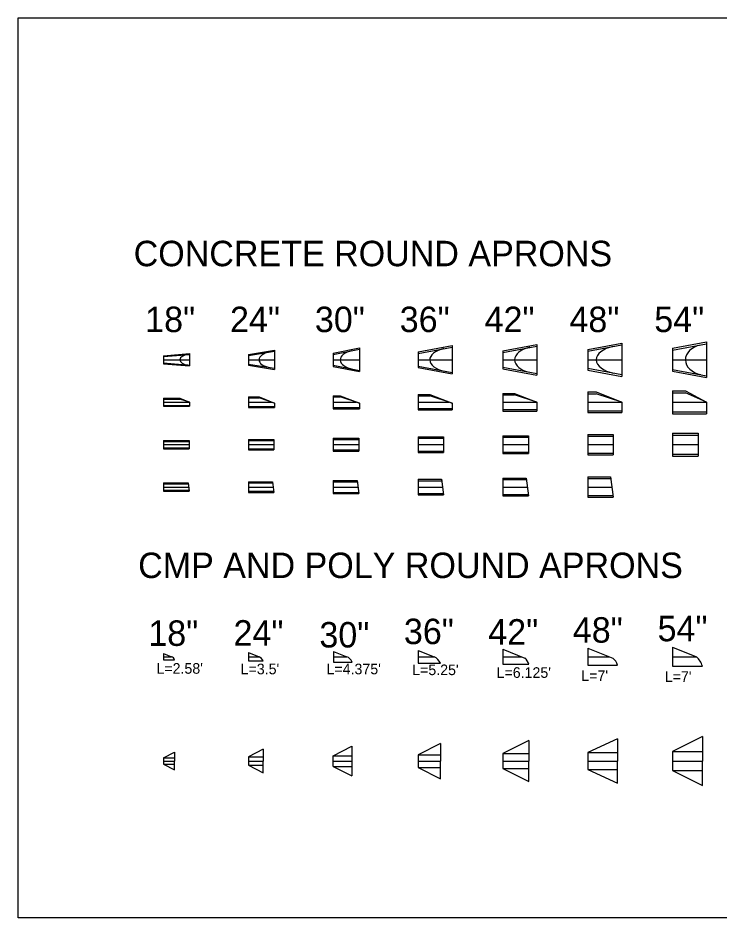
# Model space of a CAD drawing. Extents: x 14089015 to 14094575, y 8545767 to 8546666.
# Drawn here: x 14093936 to 14094101.5, y 8546454.2 to 8546666.4 of the extents above; entities that cross this region are included whole.
import ezdxf

# ---------------------------------------------------------------- set-up
doc = ezdxf.new("R2010")
doc.units = 0
doc.layers.add('CulvertExisting', color=7, linetype='Continuous')

msp = doc.modelspace()

# ---------------------------------------------------------------- linework, layer by layer
at = {"layer": 'CulvertExisting'}
for p, q in [((14094090.34, 8546588.53), (14094098.34, 8546590.03)), ((14094098.34, 8546590.03), (14094098.34, 8546581.6)), ((14093990.34, 8546587.07), (14093996.47, 8546588.07)), ((14093990.34, 8546586.81), (14093996.47, 8546587.81)), ((14093996.47, 8546588.07), (14093996.47, 8546583.56)), ((14094010.34, 8546587.36), (14094016.49, 8546588.61)), ((14094010.34, 8546587.06), (14094016.49, 8546588.31)), ((14094016.49, 8546588.61), (14094016.49, 8546583.02)), ((14094030.34, 8546587.65), (14094038.34, 8546589.15)), ((14094030.34, 8546587.31), (14094038.34, 8546588.81)), ((14094030.34, 8546587.65), (14094030.34, 8546583.98)), ((14094038.34, 8546589.15), (14094038.34, 8546582.48)), ((14094050.34, 8546587.95), (14094058.34, 8546589.45)), ((14094050.34, 8546587.56), (14094058.34, 8546589.06)), ((14094050.34, 8546587.95), (14094050.34, 8546583.68)), ((14094058.34, 8546589.45), (14094058.34, 8546582.18)), ((14094070.34, 8546588.24), (14094078.34, 8546589.74)), ((14094070.34, 8546587.81), (14094078.34, 8546589.31)), ((14094070.34, 8546588.24), (14094070.34, 8546583.39)), ((14094078.34, 8546589.74), (14094078.34, 8546581.89)), ((14094090.34, 8546588.06), (14094098.34, 8546589.56)), ((14094090.34, 8546588.53), (14094090.34, 8546583.1)), ((14093970.34, 8546586.77), (14093976.42, 8546587.27)), ((14093970.34, 8546586.56), (14093976.42, 8546587.06)), ((14093970.34, 8546586.77), (14093970.34, 8546584.85)), ((14093970.34, 8546585.81), (14093974.17, 8546585.81)), ((14093974.17, 8546585.81), (14093976.42, 8546585.81)), ((14093976.42, 8546587.27), (14093976.42, 8546584.35)), ((14093990.34, 8546587.07), (14093990.34, 8546584.56)), ((14093990.34, 8546585.81), (14093992.84, 8546585.81)), ((14093992.84, 8546585.81), (14093996.47, 8546585.81)), ((14094010.34, 8546587.36), (14094010.34, 8546584.27)), ((14094010.34, 8546585.81), (14094011.99, 8546585.81)), ((14094011.99, 8546585.81), (14094016.49, 8546585.81)), ((14094030.34, 8546585.81), (14094033.09, 8546585.81)), ((14094033.09, 8546585.81), (14094038.34, 8546585.81)), ((14094050.34, 8546585.81), (14094053.09, 8546585.81)), ((14094053.09, 8546585.81), (14094058.34, 8546585.81)), ((14094070.34, 8546585.81), (14094072.34, 8546585.81)), ((14094072.34, 8546585.81), (14094078.34, 8546585.81)), ((14094090.34, 8546585.81), (14094093.34, 8546585.81)), ((14094093.34, 8546585.81), (14094098.34, 8546585.81)), ((14093970.34, 8546585.06), (14093976.42, 8546584.56)), ((14093970.34, 8546584.85), (14093976.42, 8546584.35)), ((14093990.34, 8546584.81), (14093996.47, 8546583.81)), ((14093990.34, 8546584.56), (14093996.47, 8546583.56)), ((14094010.34, 8546584.56), (14094016.49, 8546583.31)), ((14094010.34, 8546584.27), (14094016.49, 8546583.02)), ((14094030.34, 8546584.31), (14094038.34, 8546582.81)), ((14094030.34, 8546583.98), (14094038.34, 8546582.48)), ((14094050.34, 8546584.06), (14094058.34, 8546582.56)), ((14094050.34, 8546583.68), (14094058.34, 8546582.18)), ((14094070.34, 8546583.81), (14094078.34, 8546582.31)), ((14094090.34, 8546583.56), (14094098.34, 8546582.06)), ((14094070.34, 8546583.39), (14094078.34, 8546581.89)), ((14094090.34, 8546583.1), (14094098.34, 8546581.6)), ((14093990.34, 8546577.06), (14093992.84, 8546577.06)), ((14093990.34, 8546577.06), (14093990.34, 8546574.56)), ((14093992.84, 8546577.06), (14093996.47, 8546575.6)), ((14094010.34, 8546577.35), (14094011.99, 8546577.35)), ((14094010.34, 8546577.35), (14094010.34, 8546574.27)), ((14094010.34, 8546577.06), (14094011.99, 8546577.06)), ((14094011.99, 8546577.35), (14094016.49, 8546575.56)), ((14094016.49, 8546575.56), (14094011.99, 8546577.06)), ((14094030.34, 8546577.64), (14094033.09, 8546577.64)), ((14094030.34, 8546577.64), (14094030.34, 8546573.98)), ((14094030.34, 8546577.31), (14094033.09, 8546577.31)), ((14094033.09, 8546577.64), (14094038.34, 8546575.56)), ((14094038.34, 8546575.56), (14094033.09, 8546577.31)), ((14094050.34, 8546577.89), (14094053.09, 8546577.89)), ((14094050.34, 8546577.89), (14094050.34, 8546573.74)), ((14094050.34, 8546577.56), (14094053.09, 8546577.56)), ((14094053.09, 8546577.89), (14094058.34, 8546575.81)), ((14094058.34, 8546575.81), (14094053.09, 8546577.56)), ((14094070.34, 8546578.23), (14094072.34, 8546578.23)), ((14094070.34, 8546578.23), (14094070.34, 8546573.39)), ((14094070.34, 8546577.81), (14094072.34, 8546577.81)), ((14094072.34, 8546578.23), (14094078.34, 8546575.81)), ((14094078.34, 8546575.81), (14094072.34, 8546577.81)), ((14094090.34, 8546578.52), (14094090.34, 8546573.1)), ((14094090.34, 8546578.52), (14094093.34, 8546578.52)), ((14094090.34, 8546578.06), (14094093.34, 8546578.06)), ((14094093.34, 8546578.52), (14094098.34, 8546575.81)), ((14094098.34, 8546575.81), (14094093.34, 8546578.06)), ((14093970.34, 8546576.77), (14093974.17, 8546576.77)), ((14093970.34, 8546576.77), (14093970.34, 8546574.85)), ((14093970.34, 8546576.56), (14093974.17, 8546576.56)), ((14093970.34, 8546575.81), (14093976.42, 8546575.81)), ((14093970.34, 8546575.06), (14093976.42, 8546575.06)), ((14093974.17, 8546576.77), (14093976.42, 8546575.81)), ((14093976.42, 8546575.81), (14093974.17, 8546576.56)), ((14093976.42, 8546575.81), (14093976.42, 8546574.85)), ((14093990.34, 8546576.81), (14093992.84, 8546576.81)), ((14093990.34, 8546575.81), (14093995.84, 8546575.81)), ((14093996.47, 8546575.6), (14093992.84, 8546576.81)), ((14093996.47, 8546575.6), (14093996.47, 8546574.56)), ((14094010.34, 8546575.81), (14094015.74, 8546575.81)), ((14094016.49, 8546575.56), (14094016.49, 8546574.27)), ((14094030.34, 8546575.81), (14094037.59, 8546575.81)), ((14094038.34, 8546575.56), (14094038.34, 8546573.98)), ((14094050.34, 8546575.81), (14094058.34, 8546575.81)), ((14094058.34, 8546575.81), (14094058.34, 8546573.74)), ((14094070.34, 8546575.81), (14094078.34, 8546575.81)), ((14094078.34, 8546575.81), (14094078.34, 8546573.39)), ((14094090.34, 8546575.81), (14094098.34, 8546575.81)), ((14094098.34, 8546575.81), (14094098.34, 8546573.1)), ((14093970.34, 8546574.85), (14093976.42, 8546574.85)), ((14093990.34, 8546574.81), (14093996.47, 8546574.81)), ((14093990.34, 8546574.56), (14093996.47, 8546574.56)), ((14094010.34, 8546574.56), (14094016.49, 8546574.56)), ((14094010.34, 8546574.27), (14094016.49, 8546574.27)), ((14094030.34, 8546574.31), (14094038.34, 8546574.31)), ((14094030.34, 8546573.98), (14094038.34, 8546573.98)), ((14094050.34, 8546574.06), (14094058.34, 8546574.06)), ((14094050.34, 8546573.74), (14094058.34, 8546573.74)), ((14094070.34, 8546573.81), (14094078.34, 8546573.81)), ((14094070.34, 8546573.39), (14094078.34, 8546573.39)), ((14094090.34, 8546573.56), (14094098.34, 8546573.56)), ((14094090.34, 8546573.1), (14094098.34, 8546573.1)), ((14093970.34, 8546566.77), (14093970.34, 8546564.85)), ((14093970.34, 8546566.77), (14093976.34, 8546566.77)), ((14093970.34, 8546566.56), (14093976.34, 8546566.56)), ((14093976.34, 8546566.77), (14093976.34, 8546564.85)), ((14093990.34, 8546567.06), (14093996.34, 8546567.06)), ((14093990.34, 8546567.06), (14093990.34, 8546564.56)), ((14093990.34, 8546566.81), (14093996.34, 8546566.81)), ((14093996.34, 8546567.06), (14093996.34, 8546564.56)), ((14094010.34, 8546567.35), (14094016.34, 8546567.35)), ((14094010.34, 8546567.35), (14094010.34, 8546564.27)), ((14094010.34, 8546567.06), (14094016.34, 8546567.06)), ((14094016.34, 8546567.35), (14094016.34, 8546564.27)), ((14094030.34, 8546567.64), (14094036.34, 8546567.64)), ((14094030.34, 8546567.64), (14094030.34, 8546563.98)), ((14094030.34, 8546567.31), (14094036.34, 8546567.31)), ((14094036.34, 8546567.64), (14094036.34, 8546563.98)), ((14094050.34, 8546567.89), (14094056.34, 8546567.89)), ((14094050.34, 8546567.89), (14094050.34, 8546563.74)), ((14094050.34, 8546567.56), (14094056.34, 8546567.56)), ((14094056.34, 8546567.89), (14094056.34, 8546563.74)), ((14094070.34, 8546568.23), (14094076.34, 8546568.23)), ((14094070.34, 8546568.23), (14094070.34, 8546563.39)), ((14094070.34, 8546567.81), (14094076.34, 8546567.81)), ((14094076.34, 8546568.23), (14094076.34, 8546563.39)), ((14094090.34, 8546568.52), (14094090.34, 8546563.1)), ((14094090.34, 8546568.52), (14094096.34, 8546568.52)), ((14094090.34, 8546568.06), (14094096.34, 8546568.06)), ((14094096.34, 8546568.52), (14094096.34, 8546563.1)), ((14093970.34, 8546565.81), (14093976.34, 8546565.81)), ((14093970.34, 8546565.06), (14093976.34, 8546565.06)), ((14093970.34, 8546564.85), (14093976.34, 8546564.85)), ((14093990.34, 8546565.81), (14093996.34, 8546565.81)), ((14093990.34, 8546564.81), (14093996.34, 8546564.81)), ((14093990.34, 8546564.56), (14093996.34, 8546564.56)), ((14094010.34, 8546565.81), (14094016.34, 8546565.81)), ((14094010.34, 8546564.56), (14094016.34, 8546564.56)), ((14094030.34, 8546565.81), (14094036.34, 8546565.81)), ((14094030.34, 8546564.31), (14094036.34, 8546564.31)), ((14094050.34, 8546565.81), (14094056.34, 8546565.81)), ((14094070.34, 8546565.81), (14094076.34, 8546565.81)), ((14094090.34, 8546565.81), (14094096.34, 8546565.81)), ((14094010.34, 8546564.27), (14094016.34, 8546564.27)), ((14094030.34, 8546563.98), (14094036.34, 8546563.98)), ((14094050.34, 8546564.06), (14094056.34, 8546564.06)), ((14094050.34, 8546563.74), (14094056.34, 8546563.74)), ((14094070.34, 8546563.81), (14094076.34, 8546563.81)), ((14094070.34, 8546563.39), (14094076.34, 8546563.39)), ((14094090.34, 8546563.56), (14094096.34, 8546563.56)), ((14094090.34, 8546563.1), (14094096.34, 8546563.1)), ((14094070.34, 8546558.23), (14094075.71, 8546558.23)), ((14094070.34, 8546558.23), (14094070.34, 8546553.39)), ((14094075.71, 8546558.23), (14094076.34, 8546553.39)), ((14093970.34, 8546556.77), (14093970.34, 8546554.85)), ((14093970.34, 8546556.77), (14093976.12, 8546556.77)), ((14093970.34, 8546556.56), (14093976.15, 8546556.56)), ((14093976.12, 8546556.77), (14093976.37, 8546554.86)), ((14093990.34, 8546557.06), (14093996.01, 8546557.06)), ((14093990.34, 8546557.06), (14093990.34, 8546554.56)), ((14093990.34, 8546556.81), (14093996.05, 8546556.81)), ((14093996.01, 8546557.06), (14093996.34, 8546554.56)), ((14094010.34, 8546557.35), (14094015.94, 8546557.35)), ((14094010.34, 8546557.35), (14094010.34, 8546554.27)), ((14094010.34, 8546557.06), (14094015.98, 8546557.06)), ((14094015.94, 8546557.35), (14094016.34, 8546554.27)), ((14094030.34, 8546557.64), (14094035.86, 8546557.64)), ((14094030.34, 8546557.64), (14094030.34, 8546553.98)), ((14094030.34, 8546557.31), (14094035.91, 8546557.31)), ((14094035.86, 8546557.64), (14094036.34, 8546553.98)), ((14094050.34, 8546557.89), (14094055.84, 8546557.89)), ((14094050.34, 8546557.89), (14094050.34, 8546553.74)), ((14094050.34, 8546557.56), (14094055.88, 8546557.56)), ((14094055.84, 8546557.89), (14094056.39, 8546553.74)), ((14094070.34, 8546557.81), (14094075.76, 8546557.81)), ((14093970.34, 8546555.81), (14093976.24, 8546555.81)), ((14093970.34, 8546555.06), (14093976.34, 8546555.06)), ((14093970.34, 8546554.85), (14093976.34, 8546554.85)), ((14093990.34, 8546555.81), (14093996.18, 8546555.81)), ((14093990.34, 8546554.81), (14093996.31, 8546554.81)), ((14093990.34, 8546554.56), (14093996.34, 8546554.56)), ((14094010.34, 8546555.81), (14094016.14, 8546555.81)), ((14094010.34, 8546554.56), (14094016.31, 8546554.56)), ((14094010.34, 8546554.27), (14094016.34, 8546554.27)), ((14094030.34, 8546555.81), (14094036.1, 8546555.81)), ((14094030.34, 8546554.31), (14094036.3, 8546554.31)), ((14094030.34, 8546553.98), (14094036.34, 8546553.98)), ((14094050.34, 8546555.81), (14094056.11, 8546555.81)), ((14094050.34, 8546554.06), (14094056.34, 8546554.06)), ((14094050.34, 8546553.74), (14094056.34, 8546553.74)), ((14094070.34, 8546555.81), (14094076.02, 8546555.81)), ((14094070.34, 8546553.81), (14094076.29, 8546553.81)), ((14094070.34, 8546553.39), (14094076.34, 8546553.39)), ((14094070.34, 8546517.81), (14094076.25, 8546515.45)), ((14094070.34, 8546517.81), (14094070.34, 8546513.81)), ((14094090.34, 8546518.06), (14094095.97, 8546515.81)), ((14094090.34, 8546518.06), (14094090.34, 8546513.56)), ((14093970.34, 8546516.56), (14093970.34, 8546515.06)), ((14093970.34, 8546516.56), (14093972.21, 8546515.82)), ((14093970.34, 8546515.81), (14093972.22, 8546515.81)), ((14093990.34, 8546516.81), (14093990.34, 8546514.81)), ((14093990.34, 8546516.81), (14093992.84, 8546515.81)), ((14093990.34, 8546515.81), (14093992.84, 8546515.81)), ((14094010.4, 8546517.06), (14094010.4, 8546514.56)), ((14094010.4, 8546517.06), (14094013.51, 8546515.82)), ((14094010.4, 8546515.81), (14094013.53, 8546515.81)), ((14094030.34, 8546517.31), (14094030.34, 8546514.31)), ((14094030.34, 8546517.31), (14094034.14, 8546515.79)), ((14094030.34, 8546515.81), (14094034.09, 8546515.81)), ((14094050.34, 8546517.56), (14094055.48, 8546515.51)), ((14094050.34, 8546517.56), (14094050.34, 8546514.06)), ((14094050.34, 8546515.81), (14094054.72, 8546515.81)), ((14094070.34, 8546515.81), (14094075.54, 8546515.81)), ((14094090.34, 8546515.81), (14094095.97, 8546515.81)), ((14093970.34, 8546515.06), (14093972.92, 8546515.06)), ((14093990.34, 8546514.81), (14093993.84, 8546514.81)), ((14094010.4, 8546514.56), (14094014.78, 8546514.56)), ((14094030.34, 8546514.31), (14094035.59, 8546514.31)), ((14094050.34, 8546514.06), (14094056.47, 8546514.06)), ((14094070.34, 8546513.81), (14094077.34, 8546513.81)), ((14094090.34, 8546513.56), (14094097.34, 8546513.56)), ((14094077.34, 8546496.47), (14094070.34, 8546493.22)), ((14094077.34, 8546496.47), (14094077.34, 8546491.22)), ((14094097.34, 8546496.97), (14094090.34, 8546493.47)), ((14094097.34, 8546496.97), (14094097.34, 8546491.22)), ((14094010.34, 8546492.47), (14094014.72, 8546494.72)), ((14094014.72, 8546494.72), (14094014.72, 8546487.72)), ((14094035.59, 8546495.39), (14094030.34, 8546492.72)), ((14094035.59, 8546495.39), (14094035.59, 8546491.22)), ((14094056.47, 8546496.05), (14094050.34, 8546492.97)), ((14094056.47, 8546496.05), (14094056.47, 8546491.22)), ((14093970.34, 8546491.97), (14093972.92, 8546493.3)), ((14093972.92, 8546493.3), (14093972.92, 8546491.22)), ((14093993.84, 8546494.01), (14093990.34, 8546492.22)), ((14093990.34, 8546492.22), (14093993.84, 8546492.22)), ((14093990.34, 8546492.22), (14093990.34, 8546490.22)), ((14093993.84, 8546494.01), (14093993.84, 8546491.22)), ((14094010.34, 8546492.47), (14094014.72, 8546492.47)), ((14094010.34, 8546489.97), (14094010.34, 8546492.47)), ((14094030.34, 8546492.72), (14094035.59, 8546492.72)), ((14094030.34, 8546492.72), (14094030.34, 8546489.72)), ((14094050.34, 8546492.97), (14094056.47, 8546492.97)), ((14094050.34, 8546492.97), (14094050.34, 8546489.47)), ((14094070.34, 8546493.22), (14094077.34, 8546493.22)), ((14094070.34, 8546493.22), (14094070.34, 8546491.22)), ((14094090.34, 8546493.47), (14094097.34, 8546493.47)), ((14094090.34, 8546493.47), (14094090.34, 8546488.97)), ((14093970.34, 8546491.97), (14093972.92, 8546491.97)), ((14093970.34, 8546491.97), (14093970.34, 8546490.47)), ((14093970.34, 8546491.22), (14093972.92, 8546491.22)), ((14093970.34, 8546490.47), (14093972.92, 8546490.47)), ((14093970.34, 8546490.47), (14093972.92, 8546489.14)), ((14093972.92, 8546489.14), (14093972.92, 8546491.22)), ((14093990.34, 8546491.22), (14093993.84, 8546491.22)), ((14093990.34, 8546490.22), (14093993.84, 8546490.22)), ((14093990.34, 8546490.22), (14093993.84, 8546488.43)), ((14093993.84, 8546488.43), (14093993.84, 8546491.22)), ((14094010.34, 8546491.22), (14094014.72, 8546491.22)), ((14094030.34, 8546491.22), (14094035.59, 8546491.22)), ((14094035.59, 8546487.05), (14094035.59, 8546491.22)), ((14094050.34, 8546491.22), (14094056.47, 8546491.22)), ((14094056.47, 8546486.39), (14094056.47, 8546491.22)), ((14094070.34, 8546491.22), (14094077.34, 8546491.22)), ((14094070.34, 8546491.22), (14094070.34, 8546489.22)), ((14094077.34, 8546485.97), (14094077.34, 8546491.22)), ((14094090.34, 8546491.22), (14094097.34, 8546491.22)), ((14094097.34, 8546485.47), (14094097.34, 8546491.22)), ((14094010.34, 8546489.97), (14094014.72, 8546489.97)), ((14094010.34, 8546489.97), (14094014.72, 8546487.72)), ((14094030.34, 8546489.72), (14094035.59, 8546489.72)), ((14094030.34, 8546489.72), (14094035.59, 8546487.05)), ((14094050.34, 8546489.47), (14094056.47, 8546489.47)), ((14094050.34, 8546489.47), (14094056.47, 8546486.39)), ((14094070.34, 8546489.22), (14094077.34, 8546489.22)), ((14094070.34, 8546489.22), (14094077.34, 8546485.97)), ((14094090.34, 8546488.97), (14094097.34, 8546488.97)), ((14094090.34, 8546488.97), (14094097.34, 8546485.47))]:
    msp.add_line(p, q, dxfattribs=at)
msp.add_lwpolyline([(14093936.03, 8546666.39), (14094575.33, 8546666.39), (14094575.33, 8546454.22), (14093936.03, 8546454.22)], close=True, dxfattribs=at)
for centre, radius, start, end in [((14093971.81, 8546514.72), 1.17, 17.1311, 69.6715), ((14093991.13, 8546513.1), 3.2, 32.2488, 57.7512), ((14094012.6, 8546513.64), 2.36, 23.0367, 67.4986), ((14094032.56, 8546512.79), 3.4, 26.665, 62.1679), ((14094053.38, 8546513.02), 3.26, 18.7213, 49.8517), ((14094092.29, 8546512.02), 5.29, 17.0131, 45.9188), ((14094074.67, 8546513.21), 2.74, 12.6598, 54.6475)]:
    msp.add_arc(centre, radius, start, end, dxfattribs=at)
for centre, major_axis, ratio, start_param, end_param in [((14094016.49, 8546585.81), (4.5, 0), 0.516797, 1.967696, 4.372548), ((14094038.34, 8546585.81), (5.25, 0), 0.539087, 1.943229, 4.371953), ((14094058.34, 8546585.81), (5.25, 0), 0.589894, 1.887368, 4.39014), ((14094078.34, 8546585.81), (6, 0), 0.552144, 1.909281, 4.380017), ((14094098.34, 8546585.81), (5, 0), 0.725878, 1.858842, 4.441642), ((14093976.42, 8546585.81), (2.25, 0), 0.548754, 1.713763, 4.561434), ((14093996.47, 8546585.81), (3.62, 0), 0.527355, 1.900882, 4.368644)]:
    msp.add_ellipse(centre, major_axis=major_axis, ratio=ratio, start_param=start_param, end_param=end_param, dxfattribs=at)

# ---------------------------------------------------------------- texts
for s, height, p in [('CONCRETE ROUND APRONS', 6, (14093963.29, 8546607.87)), ('18"', 6, (14093966.01, 8546592.34)), ('24"', 6, (14093986.01, 8546592.34)), ('30"', 6, (14094006.01, 8546592.34)), ('36"', 6, (14094026.01, 8546592.34)), ('42"', 6, (14094046.01, 8546592.34)), ('48"', 6, (14094066.01, 8546592.34)), ('54"', 6, (14094086.01, 8546592.34)), ('CMP AND POLY ROUND APRONS', 6, (14093964.35, 8546534.36)), ('18"', 6, (14093966.74, 8546518.37)), ('24"', 6, (14093986.83, 8546518.43)), ('30"', 6, (14094007.07, 8546517.99)), ('36"', 6, (14094026.99, 8546518.78)), ('42"', 6, (14094046.88, 8546518.67)), ('48"', 6, (14094066.81, 8546519.13)), ('54"', 6, (14094086.79, 8546519.46)), ("L=2.58'", 2.5, (14093968.66, 8546511.8)), ("L=3.5'", 2.5, (14093988.51, 8546511.68)), ("L=4.375'", 2.5, (14094008.75, 8546511.67)), ("L=5.25'", 2.5, (14094028.94, 8546511.47)), ("L=6.125'", 2.5, (14094048.84, 8546510.83)), ("L=7'", 2.5, (14094068.8, 8546510.09)), ("L=7'", 2.5, (14094088.48, 8546509.89))]:
    msp.add_text(s, height=height, dxfattribs=at).set_placement(p)

doc.saveas('drawing.dxf')
